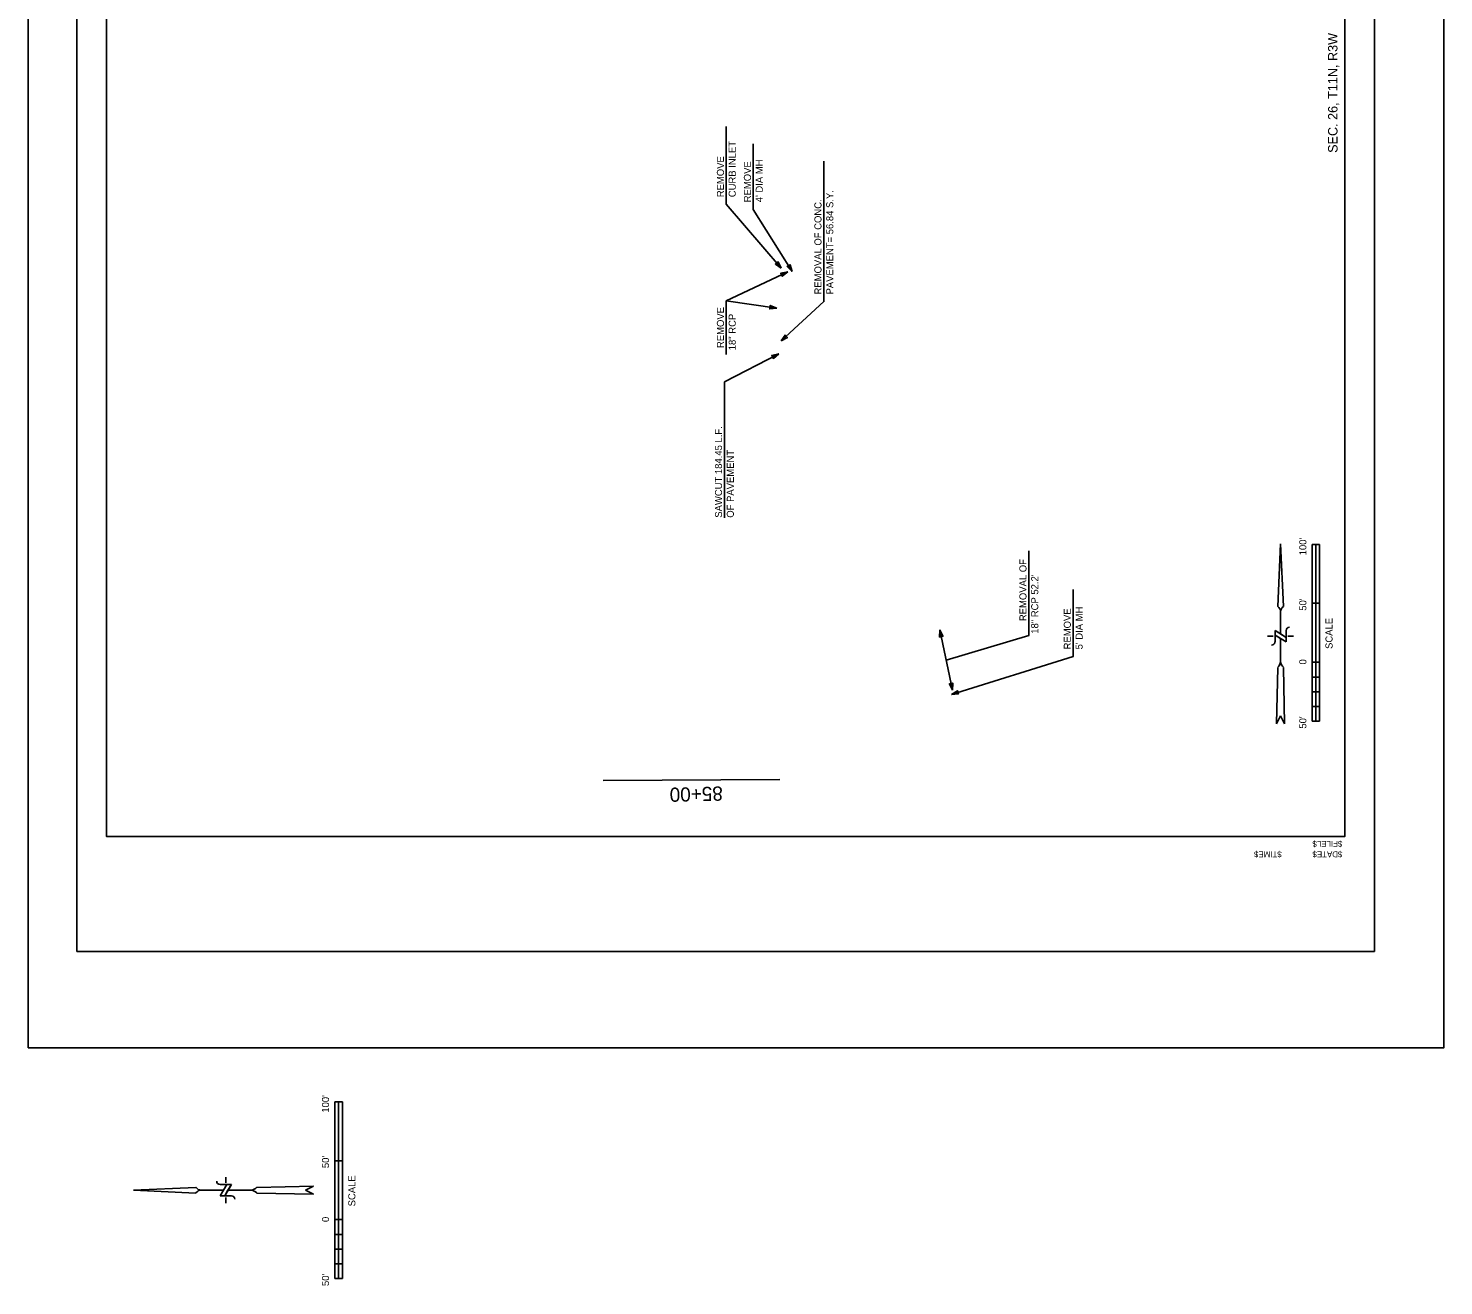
# Model space of a CAD drawing. Extents: x 2150259 to 2151459, y 143090 to 145092.
# Drawn here: x 2150259 to 2151459, y 143090 to 144157 of the extents above; entities that cross this region are included whole.
import ezdxf

# ---------------------------------------------------------------- set-up
doc = ezdxf.new("R2010")
doc.units = 0
for name, color, linetype in [('PR_Removal_Txt', 7, 'Continuous'), ('PR_Txt', 7, 'Continuous'), ('SHT_Match_Lines', 7, 'Continuous'), ('SHT_North_Arrow', 7, 'Continuous'), ('SHT_Plot_Shape_Full', 7, 'Continuous'), ('SHT_Plot_Shape_Half', 7, 'Continuous'), ('SHT_Plot_Stamp', 7, 'Continuous'), ('SHT_Scale', 7, 'Continuous'), ('SHT_Sheet_Border', 7, 'Continuous'), ('SHT_Sheet_Txt', 7, 'Continuous')]:
    doc.layers.add(name, color=color, linetype=linetype)

msp = doc.modelspace()

# ---------------------------------------------------------------- linework, layer by layer
at = {"layer": 'PR_Removal_Txt'}
for p, q in [((2150851, 144013.5), (2150851, 144073.4)), ((2150873.9, 144009.2), (2150873.9, 144058.7)), ((2150933.7, 143931), (2150933.7, 144044)), ((2150851, 143925.5), (2150903.1, 143950.2)), ((2150851, 143919.5), (2150851, 143880.1)), ((2150849.4, 143741.7), (2150849.4, 143850.8)), ((2151107.5, 143713.5), (2151107.5, 143647.8)), ((2151145.1, 143630), (2151145.1, 143680.9)), ((2151042.7, 143595.5), (2151032, 143646.5))]:
    msp.add_line(p, q, dxfattribs=at)
for points in [[(2150897.6, 143953.3), (2150851, 144007.5), (2150851, 144013.5)], [(2150906.9, 143950.5), (2150873.9, 144003.2), (2150873.9, 144009.2)], [(2150897.5, 143891.6), (2150933.7, 143925), (2150933.7, 143931)], [(2150893.9, 143919.4), (2150851, 143925.5), (2150851, 143919.5)], [(2150895.4, 143880.7), (2150849.4, 143856.8), (2150849.4, 143850.8)], [(2151037.4, 143621), (2151107.5, 143641.8), (2151107.5, 143647.8)], [(2151041.8, 143591.8), (2151145.1, 143624), (2151145.1, 143630)]]:
    msp.add_lwpolyline(points, dxfattribs=at)
for points in [[(2150897.6, 143953.3), (2150892.7, 143956.8), (2150894.9, 143958.7)], [(2150906.9, 143950.5), (2150902.6, 143954.7), (2150905.1, 143956.2)], [(2150903.1, 143950.2), (2150897.2, 143949), (2150898.5, 143946.4)], [(2150893.9, 143919.4), (2150887.9, 143918.8), (2150888.3, 143921.7)], [(2150897.5, 143891.6), (2150900.8, 143896.6), (2150902.8, 143894.5)], [(2150895.4, 143880.7), (2150890.9, 143876.8), (2150889.5, 143879.3)], [(2151032, 143646.5), (2151031.8, 143640.5), (2151034.6, 143641.1)], [(2151042.7, 143595.5), (2151043, 143601.5), (2151040.1, 143600.9)], [(2151041.8, 143591.8), (2151046.9, 143595), (2151047.8, 143592.2)]]:
    msp.add_lwpolyline(points, close=True, dxfattribs=at)
at = {"layer": 'SHT_Match_Lines'}
msp.add_line((2150896.5, 143519.7), (2150746.5, 143518.8), dxfattribs=at)
at = {"layer": 'SHT_North_Arrow'}
for p, q in [((2151318.6, 143666.5), (2151321, 143719.4)), ((2151321, 143719.4), (2151318.6, 143666.5)), ((2151321, 143719.4), (2151323.4, 143666.5)), ((2151323.4, 143666.5), (2151321, 143719.4)), ((2151321, 143643.1), (2151321, 143661.8)), ((2151314.7, 143641.2), (2151309.9, 143641.2)), ((2151325.8, 143640.2), (2151316.2, 143646)), ((2151316.2, 143646), (2151325.8, 143640.2)), ((2151316.2, 143646), (2151316.2, 143636.4)), ((2151321, 143643.1), (2151316.2, 143646)), ((2151316.2, 143646), (2151316.2, 143642.2)), ((2151325.8, 143636.4), (2151316.2, 143642.2)), ((2151325.8, 143640.2), (2151321, 143643.1)), ((2151325.8, 143646), (2151325.8, 143636.4)), ((2151325.8, 143636.4), (2151325.8, 143640.2)), ((2151332, 143641.2), (2151327.2, 143641.2)), ((2151321, 143619.6), (2151321, 143639.3)), ((2151317.6, 143566.8), (2151318.6, 143614.8)), ((2151318.6, 143614.8), (2151317.6, 143566.8)), ((2151324.3, 143566.8), (2151323.4, 143614.8)), ((2151324.3, 143566.8), (2151323.4, 143614.8)), ((2151317.6, 143566.8), (2151321, 143573.6)), ((2151317.6, 143566.8), (2151321, 143573.6)), ((2151321, 143573.6), (2151324.3, 143566.8)), ((2151321, 143573.6), (2151324.3, 143566.8)), ((2150348.4, 143171.4), (2150401.3, 143173.8)), ((2150401.3, 143173.8), (2150348.4, 143171.4)), ((2150421.8, 143176.2), (2150431.4, 143176.2)), ((2150427.6, 143176.2), (2150421.8, 143166.6)), ((2150421.8, 143166.6), (2150427.6, 143176.2)), ((2150427.6, 143176.2), (2150424.7, 143171.4)), ((2150431.4, 143176.2), (2150425.7, 143166.6)), ((2150426.6, 143182.5), (2150426.6, 143177.7)), ((2150431.4, 143176.2), (2150427.6, 143176.2)), ((2150501, 143174.8), (2150453, 143173.8)), ((2150501, 143174.8), (2150453, 143173.8)), ((2150494.3, 143171.4), (2150501, 143174.8)), ((2150494.3, 143171.4), (2150501, 143174.8)), ((2150401.3, 143169), (2150348.4, 143171.4)), ((2150348.4, 143171.4), (2150401.3, 143169)), ((2150424.7, 143171.4), (2150406, 143171.4)), ((2150424.7, 143171.4), (2150421.8, 143166.6)), ((2150421.8, 143166.6), (2150431.4, 143166.6)), ((2150421.8, 143166.6), (2150425.7, 143166.6)), ((2150426.6, 143165.2), (2150426.6, 143160.4)), ((2150448.2, 143171.4), (2150428.5, 143171.4)), ((2150501, 143168.1), (2150453, 143169)), ((2150453, 143169), (2150501, 143168.1)), ((2150501, 143168.1), (2150494.3, 143171.4)), ((2150501, 143168.1), (2150494.3, 143171.4))]:
    msp.add_line(p, q, dxfattribs=at)
for points in [[(2151316.2, 143642.2), (2151321, 143639.3), (2151325.8, 143636.4)], [(2151321, 143619.6), (2151321, 143619.6), (2151321, 143619.6)], [(2150425.7, 143166.6), (2150428.5, 143171.4), (2150431.4, 143176.2)], [(2150448.2, 143171.4), (2150448.2, 143171.4), (2150448.2, 143171.4)]]:
    msp.add_lwpolyline(points, dxfattribs=at)
for centre, radius, start, end in [((2151315.2, 143661.8), 5.76, 360, 54.3802), ((2151315.2, 143661.8), 5.76, 360, 54.3802), ((2151326.7, 143661.8), 5.76, 125.6198, 180), ((2151326.7, 143661.8), 5.76, 125.6198, 180), ((2151328.6, 143646), 2.88, 90, 180), ((2151313.3, 143636.4), 2.88, 270, 360), ((2151312.6, 143620.8), 8.43, 314.9567, 352.4189), ((2151312.6, 143620.8), 8.43, 314.9567, 352.059), ((2151329.3, 143620.8), 8.43, 187.5811, 225.0433), ((2151329.3, 143620.8), 8.43, 187.941, 225.0433), ((2150406, 143177.2), 5.76, 215.6198, 270), ((2150406, 143177.2), 5.76, 215.6198, 270), ((2150421.8, 143179.1), 2.88, 180, 270), ((2150447, 143179.8), 8.43, 277.5811, 315.0433), ((2150447, 143179.8), 8.43, 277.941, 315.0433), ((2150406, 143165.7), 5.76, 90, 144.3802), ((2150406, 143165.7), 5.76, 90, 144.3802), ((2150431.4, 143163.7), 2.88, 0, 90), ((2150447, 143163.1), 8.43, 44.9567, 82.4189), ((2150447, 143163.1), 8.43, 44.9567, 82.059)]:
    msp.add_arc(centre, radius, start, end, dxfattribs=at)
at = {"layer": 'SHT_Plot_Shape_Full'}
msp.add_lwpolyline([(2150259.2, 143292), (2150259.2, 145092), (2151459.2, 145092), (2151459.2, 143292)], close=True, dxfattribs=at)
at = {"layer": 'SHT_Plot_Shape_Half'}
msp.add_lwpolyline([(2150300.5, 143373.9), (2150300.5, 145073.9), (2151400.5, 145073.9), (2151400.5, 143373.9)], close=True, dxfattribs=at)
at = {"layer": 'SHT_Scale'}
for p, q in [((2151347.8, 143719.1), (2151350.9, 143719.1)), ((2151347.8, 143569.1), (2151347.8, 143719.1)), ((2151350.9, 143719.1), (2151354, 143719.1)), ((2151350.9, 143619.1), (2151350.9, 143719.1)), ((2151354, 143719.1), (2151350.9, 143719.1)), ((2151350.9, 143719.1), (2151350.9, 143669.1)), ((2151354, 143569.1), (2151354, 143719.1)), ((2151354, 143669.1), (2151354, 143719.1)), ((2151350.9, 143669.1), (2151347.8, 143669.1)), ((2151350.9, 143669.1), (2151347.8, 143669.1)), ((2151347.8, 143669.1), (2151347.8, 143619.1)), ((2151354, 143669.1), (2151350.9, 143669.1)), ((2151350.9, 143619.1), (2151350.9, 143669.1)), ((2151350.9, 143669.1), (2151354, 143669.1)), ((2151350.9, 143619.1), (2151347.8, 143619.1)), ((2151347.8, 143619.1), (2151350.9, 143619.1)), ((2151354, 143619.1), (2151350.9, 143619.1)), ((2151350.9, 143606.6), (2151350.9, 143619.1)), ((2151354, 143619.1), (2151350.9, 143619.1)), ((2151350.9, 143619.1), (2151350.9, 143606.6)), ((2151354, 143606.6), (2151354, 143619.1)), ((2151347.8, 143606.6), (2151354, 143606.6)), ((2151350.9, 143606.6), (2151347.8, 143606.6)), ((2151347.8, 143606.6), (2151347.8, 143594.1)), ((2151350.9, 143594.1), (2151350.9, 143606.6)), ((2151350.9, 143594.1), (2151350.9, 143606.6)), ((2151350.9, 143606.6), (2151354, 143606.6)), ((2151347.8, 143594.1), (2151354, 143594.1)), ((2151347.8, 143594.1), (2151354, 143594.1)), ((2151347.8, 143594.1), (2151350.9, 143594.1)), ((2151350.9, 143581.6), (2151350.9, 143594.1)), ((2151354, 143594.1), (2151350.9, 143594.1)), ((2151350.9, 143594.1), (2151350.9, 143581.6)), ((2151354, 143581.6), (2151354, 143594.1)), ((2151347.8, 143581.6), (2151354, 143581.6)), ((2151350.9, 143581.6), (2151347.8, 143581.6)), ((2151347.8, 143581.6), (2151347.8, 143569.1)), ((2151350.9, 143569.1), (2151350.9, 143581.6)), ((2151350.9, 143569.1), (2151350.9, 143581.6)), ((2151350.9, 143581.6), (2151354, 143581.6)), ((2151347.8, 143569.1), (2151354, 143569.1)), ((2151347.8, 143569.1), (2151350.9, 143569.1)), ((2150519.2, 143246.4), (2150522.3, 143246.4)), ((2150519.2, 143096.4), (2150519.2, 143246.4)), ((2150522.3, 143246.4), (2150525.5, 143246.4)), ((2150522.3, 143146.4), (2150522.3, 143246.4)), ((2150525.5, 143246.4), (2150522.3, 143246.4)), ((2150522.3, 143246.4), (2150522.3, 143196.4)), ((2150525.5, 143096.4), (2150525.5, 143246.4)), ((2150525.5, 143196.4), (2150525.5, 143246.4)), ((2150522.3, 143196.4), (2150519.2, 143196.4)), ((2150522.3, 143196.4), (2150519.2, 143196.4)), ((2150519.2, 143196.4), (2150519.2, 143146.4)), ((2150525.5, 143196.4), (2150522.3, 143196.4)), ((2150522.3, 143146.4), (2150522.3, 143196.4)), ((2150522.3, 143196.4), (2150525.5, 143196.4)), ((2150522.3, 143146.4), (2150519.2, 143146.4)), ((2150519.2, 143146.4), (2150522.3, 143146.4)), ((2150525.5, 143146.4), (2150522.3, 143146.4)), ((2150522.3, 143133.9), (2150522.3, 143146.4)), ((2150525.5, 143146.4), (2150522.3, 143146.4)), ((2150522.3, 143146.4), (2150522.3, 143133.9)), ((2150525.5, 143133.9), (2150525.5, 143146.4)), ((2150519.2, 143133.9), (2150525.5, 143133.9)), ((2150522.3, 143133.9), (2150519.2, 143133.9)), ((2150519.2, 143133.9), (2150519.2, 143121.4)), ((2150522.3, 143121.4), (2150522.3, 143133.9)), ((2150522.3, 143121.4), (2150522.3, 143133.9)), ((2150522.3, 143133.9), (2150525.5, 143133.9)), ((2150519.2, 143121.4), (2150525.5, 143121.4)), ((2150519.2, 143121.4), (2150525.5, 143121.4)), ((2150519.2, 143121.4), (2150522.3, 143121.4)), ((2150522.3, 143108.9), (2150522.3, 143121.4)), ((2150525.5, 143121.4), (2150522.3, 143121.4)), ((2150522.3, 143121.4), (2150522.3, 143108.9)), ((2150525.5, 143108.9), (2150525.5, 143121.4)), ((2150519.2, 143108.9), (2150525.5, 143108.9)), ((2150522.3, 143108.9), (2150519.2, 143108.9)), ((2150519.2, 143108.9), (2150519.2, 143096.4)), ((2150522.3, 143096.4), (2150522.3, 143108.9)), ((2150522.3, 143096.4), (2150522.3, 143108.9)), ((2150522.3, 143108.9), (2150525.5, 143108.9)), ((2150519.2, 143096.4), (2150525.5, 143096.4)), ((2150519.2, 143096.4), (2150522.3, 143096.4))]:
    msp.add_line(p, q, dxfattribs=at)
at = {"layer": 'SHT_Sheet_Border'}
msp.add_lwpolyline([(2151375.5, 145046.4), (2151375.5, 143471.4), (2150325.5, 143471.4), (2150325.5, 145046.4)], close=True, dxfattribs=at)

# ---------------------------------------------------------------- texts
at = {"layer": 'PR_Removal_Txt'}
for s, p in [('CURB INLET', (2150859, 144013.5)), ('REMOVE', (2150849, 144013.5)), ('REMOVE', (2150871.9, 144009.2)), ("4' DIA MH", (2150881.9, 144009.2)), ('PAVEMENT= 56.84 S.Y.', (2150941.7, 143931)), ('REMOVAL OF CONC.', (2150931.7, 143931)), ('REMOVE', (2150849, 143885.6)), ('18" RCP', (2150859, 143883.7)), ('SAWCUT 184.45 L.F. ', (2150847.4, 143741.7)), ('OF PAVEMENT', (2150857.4, 143741.7)), ('REMOVAL OF ', (2151105.5, 143654)), ('18" RCP 52.2\'', (2151115.5, 143643.3)), ('REMOVE', (2151143.1, 143630)), ("5' DIA MH", (2151153.1, 143630))]:
    msp.add_text(s, height=6, rotation=90, dxfattribs=at).set_placement(p)
at = {"layer": 'PR_Txt'}
msp.add_text('85+00', height=12, rotation=181.4099, dxfattribs=at).set_placement((2150847.9, 143513.8))
at = {"layer": 'SHT_Plot_Stamp'}
for s, p in [('$FILEL$', (2151373.3, 143467.6)), ('$TIME$', (2151321.9, 143458.7)), ('$DATE$', (2151373.3, 143458.7))]:
    msp.add_text(s, height=5, rotation=180, dxfattribs=at).set_placement(p)
at = {"layer": 'SHT_Scale'}
for s, p in [("100'", (2151342.8, 143709.8)), ("50'", (2151342.8, 143662.8)), ('SCALE', (2151365, 143630.4)), ('0', (2151342.8, 143617.2)), ("50'", (2151342.8, 143562.8)), ("100'", (2150514.2, 143237.1)), ("50'", (2150514.2, 143190.1)), ('SCALE', (2150536.5, 143157.7)), ('0', (2150514.2, 143144.4)), ("50'", (2150514.2, 143090.1))]:
    msp.add_text(s, height=6, rotation=90, dxfattribs=at).set_placement(p)
at = {"layer": 'SHT_Sheet_Txt'}
msp.add_text('SEC. 26, T11N, R3W', height=8, rotation=90.027, dxfattribs=at).set_placement((2151369.2, 144051.1))

doc.saveas('drawing.dxf')
